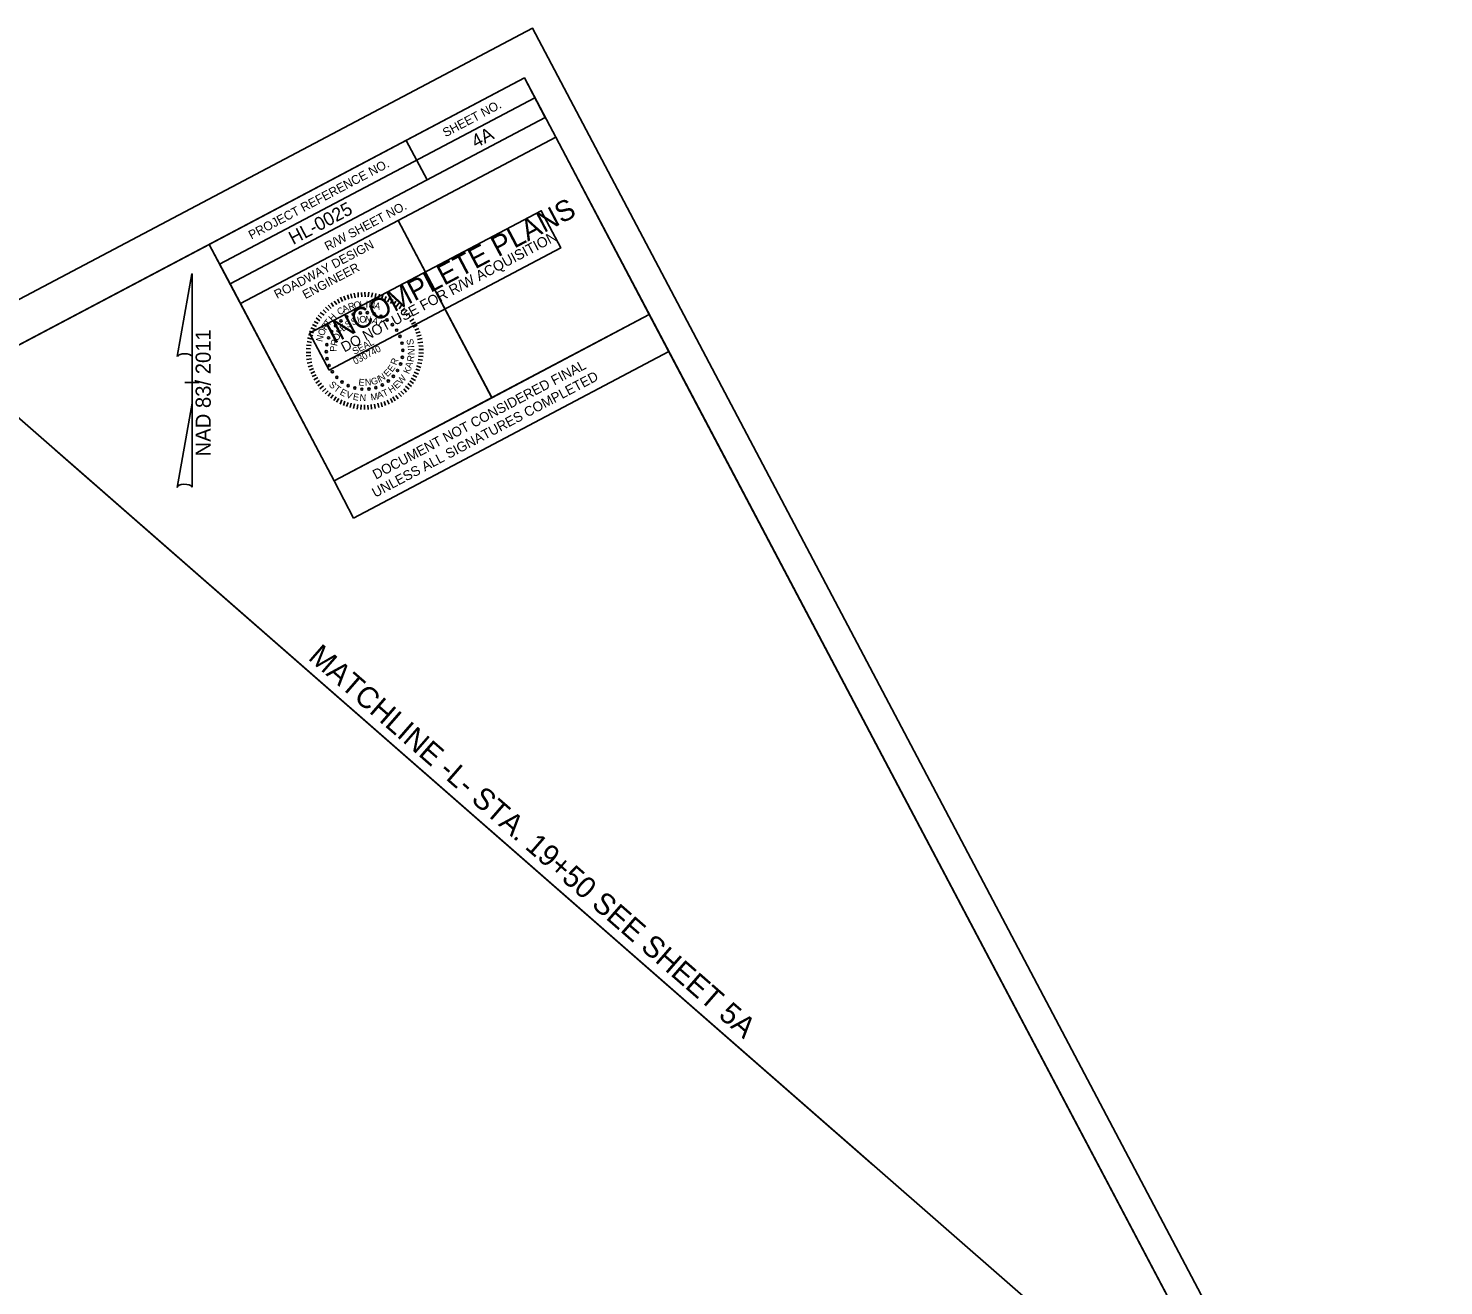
# Model space of a CAD drawing. Extents: x 1486642 to 1489051, y 497560 to 499336.
# Drawn here: x 1488257 to 1489051, y 498631 to 499336 of the extents above; entities that cross this region are included whole.
import ezdxf

# ---------------------------------------------------------------- set-up
doc = ezdxf.new("R2010")
doc.units = 0
for name, color, linetype in [('Matchline', 7, 'Continuous'), ('Matchline Text', 7, 'Continuous'), ('Old_Level_9', 7, 'Continuous'), ('Prop North Arrow NAD83 for Plan Sheets CELL', 7, 'Continuous'), ('Sheet Border Standard 30in CELL', 7, 'Continuous'), ('Sheet Clip Boundary CELL', 7, 'Continuous'), ('Sheet Data Field CELL', 7, 'Continuous'), ('Sheet Plan CELL', 7, 'Continuous'), ('Sheet Plot Border Outside CELL', 7, 'Continuous'), ('Sheet Sticker Exception Certification CELL', 7, 'Continuous'), ('Sheet Sticker Incomplete CELL', 7, 'Continuous')]:
    doc.layers.add(name, color=color, linetype=linetype)

msp = doc.modelspace()

# ---------------------------------------------------------------- linework, layer by layer
at = {"layer": 'Matchline'}
msp.add_line((1488271.73, 499099.83), (1488730.85, 498698.62), dxfattribs=at)
at = {"layer": 'Old_Level_9'}
for p, q in [((1488430.13, 499184.48), (1488431.35, 499182.18)), ((1488431.99, 499185.46), (1488432.94, 499183.02)), ((1488433.81, 499186.08), (1488434.75, 499183.87)), ((1488435.81, 499186.8), (1488436.49, 499184.44)), ((1488437.67, 499187.33), (1488438.18, 499184.88)), ((1488439.63, 499187.69), (1488440.14, 499185.24)), ((1488441.77, 499188.14), (1488441.83, 499185.46)), ((1488443.65, 499188.23), (1488443.93, 499185.77)), ((1488445.61, 499188.36), (1488445.67, 499185.68)), ((1488447.76, 499188.36), (1488447.46, 499185.72)), ((1488449.78, 499187.96), (1488449.39, 499185.49)), ((1488451.76, 499187.65), (1488451.28, 499185.13)), ((1488453.78, 499187.24), (1488453.21, 499184.9)), ((1488455.62, 499186.75), (1488454.92, 499184.23)), ((1488457.61, 499185.99), (1488456.68, 499183.68)), ((1488459.51, 499185.18), (1488458.3, 499182.96)), ((1488420.55, 499176.93), (1488422.73, 499175.37)), ((1488422.13, 499178.44), (1488423.87, 499176.65)), ((1488423.53, 499179.86), (1488425.31, 499177.98)), ((1488425.02, 499181.1), (1488426.58, 499179.21)), ((1488426.74, 499182.35), (1488428.03, 499180.32)), ((1488428.37, 499183.32), (1488429.76, 499181.34)), ((1488461.23, 499184.28), (1488460.02, 499182.06)), ((1488462.99, 499183.29), (1488461.65, 499181.11)), ((1488464.72, 499182.16), (1488463.11, 499180.07)), ((1488466.22, 499181.03), (1488464.83, 499178.94)), ((1488467.91, 499179.55), (1488465.98, 499177.63)), ((1488469.32, 499178.15), (1488467.44, 499176.36)), ((1488470.65, 499176.7), (1488468.68, 499175.09)), ((1488416.18, 499170.22), (1488418.44, 499169.15)), ((1488417.08, 499171.94), (1488419.43, 499170.69)), ((1488418.2, 499173.88), (1488420.38, 499172.32)), ((1488419.42, 499175.43), (1488421.29, 499173.82)), ((1488471.81, 499175.16), (1488469.92, 499173.6)), ((1488472.96, 499173.4), (1488470.8, 499171.92)), ((1488474.03, 499171.59), (1488471.82, 499170.42)), ((1488474.92, 499169.91), (1488472.71, 499168.74)), ((1488413.17, 499160.71), (1488415.6, 499160.18)), ((1488413.4, 499162.64), (1488415.87, 499162.02)), ((1488413.98, 499164.53), (1488416.36, 499163.87)), ((1488414.52, 499166.51), (1488416.82, 499165.58)), ((1488415.32, 499168.41), (1488417.72, 499167.3)), ((1488475.81, 499168), (1488473.6, 499167.06)), ((1488476.62, 499166.05), (1488474.26, 499165.38)), ((1488477.24, 499164.23), (1488474.7, 499163.69)), ((1488477.68, 499162.32), (1488475.14, 499161.77)), ((1488412.59, 499156.67), (1488415.14, 499156.55)), ((1488412.59, 499154.52), (1488415.27, 499154.58)), ((1488412.72, 499152.56), (1488415.31, 499152.8)), ((1488412.81, 499158.6), (1488415.37, 499158.48)), ((1488478.09, 499160.27), (1488475.37, 499159.85)), ((1488478.4, 499154.11), (1488475.8, 499154.32)), ((1488478.31, 499158.13), (1488475.81, 499158.16)), ((1488478.4, 499156.25), (1488475.94, 499156.2)), ((1488412.9, 499150.51), (1488415.58, 499151.01)), ((1488413.26, 499148.55), (1488415.8, 499149.09)), ((1488413.8, 499146.45), (1488416.24, 499147.18)), ((1488414.42, 499144.63), (1488416.77, 499145.54)), ((1488476.43, 499144.35), (1488474.17, 499145.2)), ((1488477.06, 499146.16), (1488474.58, 499147)), ((1488477.55, 499148.23), (1488475.12, 499148.75)), ((1488477.95, 499150.25), (1488475.44, 499150.51)), ((1488478.35, 499152.27), (1488475.67, 499152.43)), ((1488415.22, 499142.68), (1488417.57, 499143.81)), ((1488416.02, 499140.96), (1488418.33, 499141.95)), ((1488417, 499139.1), (1488419.12, 499140.44)), ((1488418.03, 499137.38), (1488420.18, 499138.86)), ((1488419.14, 499135.7), (1488421.16, 499137.22)), ((1488471.75, 499135.44), (1488469.65, 499137.05)), ((1488472.83, 499137.03), (1488470.78, 499138.55)), ((1488473.96, 499138.75), (1488471.6, 499140)), ((1488474.76, 499140.65), (1488472.5, 499141.72)), ((1488475.75, 499142.42), (1488473.27, 499143.48)), ((1488420.34, 499134.07), (1488422.27, 499135.77)), ((1488421.75, 499132.67), (1488423.6, 499134.33)), ((1488423.26, 499131.32), (1488425.06, 499133.06)), ((1488424.9, 499129.93), (1488426.38, 499131.84)), ((1488426.4, 499128.8), (1488427.83, 499130.8)), ((1488428.09, 499127.54), (1488429.56, 499129.67)), ((1488429.72, 499126.59), (1488431.05, 499128.77)), ((1488462.67, 499127.36), (1488461.28, 499129.57)), ((1488464.34, 499128.47), (1488462.96, 499130.46)), ((1488466.06, 499129.72), (1488464.45, 499131.7)), ((1488467.51, 499131.05), (1488465.85, 499132.89)), ((1488469, 499132.29), (1488467.35, 499134.13)), ((1488470.44, 499133.84), (1488468.39, 499135.59)), ((1488431.71, 499125.6), (1488432.73, 499127.95)), ((1488433.51, 499124.75), (1488434.35, 499127.23)), ((1488435.32, 499124.12), (1488436.2, 499126.51)), ((1488437.39, 499123.63), (1488437.91, 499126.05)), ((1488439.23, 499123.13), (1488439.67, 499125.74)), ((1488441.25, 499122.73), (1488441.6, 499125.29)), ((1488443.36, 499122.6), (1488443.48, 499125.15)), ((1488445.33, 499122.51), (1488445.32, 499125.1)), ((1488447.34, 499122.55), (1488447.29, 499125.01)), ((1488449.39, 499122.73), (1488449.16, 499125.32)), ((1488451.4, 499123), (1488450.99, 499125.49)), ((1488453.45, 499123.63), (1488452.77, 499125.98)), ((1488455.36, 499124.07), (1488454.63, 499126.52)), ((1488457.18, 499124.69), (1488456.32, 499126.96)), ((1488459.13, 499125.5), (1488458, 499127.84)), ((1488461.03, 499126.39), (1488459.87, 499128.6))]:
    msp.add_line(p, q, dxfattribs=at)
for centre in [(1488439.13, 499175.89), (1488443.01, 499176.7), (1488446.97, 499176.78), (1488450.89, 499176.13), (1488429.25, 499169.5), (1488432.13, 499172.23), (1488435.46, 499174.39), (1488454.61, 499174.77), (1488458.02, 499172.75), (1488461.01, 499170.14), (1488425.23, 499162.71), (1488426.93, 499166.29), (1488463.46, 499167.02), (1488465.3, 499163.51), (1488423.93, 499154.92), (1488424.22, 499158.87), (1488466.46, 499159.72), (1488466.9, 499155.77), (1488424.38, 499150.98), (1488425.54, 499147.19), (1488463.91, 499144.4), (1488465.61, 499147.98), (1488466.61, 499151.82), (1488427.38, 499143.67), (1488429.83, 499140.56), (1488432.81, 499137.94), (1488455.38, 499136.31), (1488458.71, 499138.46), (1488461.58, 499141.19), (1488436.22, 499135.92), (1488439.95, 499134.57), (1488443.86, 499133.92), (1488447.83, 499133.99), (1488451.71, 499134.8)]:
    msp.add_circle(centre, 0.63, dxfattribs=at)
at = {"layer": 'Prop North Arrow NAD83 for Plan Sheets CELL'}
for p, q in [((1488340.33, 499152.33), (1488348.53, 499198.68)), ((1488348.58, 499198.68), (1488348.53, 499198.68)), ((1488348.58, 499198.68), (1488348.53, 499198.68)), ((1488348.58, 499198.68), (1488348.58, 499150.88)), ((1488348.58, 499126.08), (1488348.58, 499152.28)), ((1488348.58, 499150.88), (1488348.58, 499152.23)), ((1488344.58, 499137.68), (1488344.53, 499137.68)), ((1488348.13, 499137.68), (1488344.58, 499137.68)), ((1488344.63, 499137.68), (1488352.63, 499137.68)), ((1488348.58, 499126.08), (1488340.23, 499078.83)), ((1488348.63, 499079.03), (1488348.58, 499126.08))]:
    msp.add_line(p, q, dxfattribs=at)
for centre, start_param, end_param in [((1488344.46, 499151.83), 0.216388, 2.908219), ((1488344.46, 499078.66), 0.201328, 3.141593)]:
    msp.add_ellipse(centre, major_axis=(4.23, -0.03), ratio=0.461098, start_param=start_param, end_param=end_param, dxfattribs=at)
at = {"layer": 'Sheet Border Standard 30in CELL'}
msp.add_line((1488369.9, 499192.95), (1488375.74, 499181.9), dxfattribs=at)
at = {"layer": 'Sheet Clip Boundary CELL'}
msp.add_lwpolyline([(1487208.67, 498608.12), (1488222.07, 499143.22), (1488965.38, 498493.67), (1489025.4, 498380.01), (1487698.94, 497679.61)], close=True, dxfattribs=at)
at = {"layer": 'Sheet Plan CELL'}
for p, q in [((1488364.06, 499204.02), (1488540.97, 499297.41)), ((1488369.93, 499192.94), (1488546.81, 499286.36)), ((1488468.8, 499273.43), (1488480.51, 499251.34)), ((1488464.23, 499228.61), (1488516.75, 499129.17)), ((1488369.93, 499192.94), (1488375.76, 499181.89))]:
    msp.add_line(p, q, dxfattribs=at)
for points in [[(1488535.14, 499308.53), (1487208.67, 498608.12), (1487698.94, 497679.61), (1489025.4, 498380.01)], [(1488358.21, 499215.12), (1488535.14, 499308.53), (1488546.81, 499286.36), (1488369.93, 499192.94)], [(1488464.23, 499228.61), (1488552.64, 499275.31), (1488605.19, 499175.82), (1488516.77, 499129.11)], [(1488375.76, 499181.89), (1488464.23, 499228.61), (1488516.77, 499129.11), (1488428.29, 499082.43)], [(1487698.94, 497679.61), (1487208.66, 498608.09), (1488358.21, 499215.12), (1488428.29, 499082.43), (1488605.19, 499175.82), (1489025.4, 498380.01)]]:
    msp.add_lwpolyline(points, close=True, dxfattribs=at)
at = {"layer": 'Sheet Plot Border Outside CELL'}
msp.add_lwpolyline([(1487562.23, 497581.96), (1489050.94, 498368.04), (1488539.66, 499336.34), (1487050.94, 498550.27)], close=True, dxfattribs=at)
at = {"layer": 'Sheet Sticker Exception Certification CELL'}
for p, q in [((1488428.29, 499082.43), (1488605.18, 499175.83)), ((1488605.19, 499175.82), (1488616.16, 499155.04)), ((1488616.16, 499155.05), (1488439.27, 499061.65)), ((1488439.27, 499061.65), (1488428.29, 499082.43))]:
    msp.add_line(p, q, dxfattribs=at)
at = {"layer": 'Sheet Sticker Incomplete CELL'}
msp.add_lwpolyline([(1488425.5, 499144.55), (1488414.53, 499165.33), (1488544.52, 499233.97), (1488555.49, 499213.19)], close=True, dxfattribs=at)

# ---------------------------------------------------------------- texts
at = {"layer": 'Matchline Text'}
msp.add_text('MATCHLINE -L- STA. 19+50 SEE SHEET 5A', height=12, rotation=318.92761, dxfattribs=at).set_placement((1488413.21, 498982.68))
at = {"layer": 'Old_Level_9'}
for s, height, rotation, p in [('H', 3.78, 45.57844, (1488427.42, 499171.63)), ('C', 3.78, 32.77501, (1488431.41, 499175.21)), ('A', 3.78, 25.80995, (1488433.88, 499176.74)), ('R', 3.78, 17.85665, (1488436.89, 499178.1)), ('O', 3.78, 10.92189, (1488439.69, 499179.01)), ('L', 3.78, 3.581, (1488442.77, 499179.62)), ('I', 3.78, 358.64105, (1488445.98, 499179.73)), ('N', 3.78, 352.73893, (1488447.46, 499179.72)), ('A', 3.78, 344.84016, (1488450.56, 499179.21)), ('R', 3.78, 60.01054, (1488423.86, 499166.58)), ('T', 3.78, 53.27087, (1488425.33, 499168.94)), ('F', 3.76, 54.23505, (1488432.15, 499163.95)), ('E', 3.76, 44.42402, (1488433.59, 499165.95)), ('S', 3.76, 32.30312, (1488435.86, 499168.06)), ('S', 3.76, 20.87655, (1488438.65, 499169.64)), ('I', 3.76, 13.31716, (1488441.66, 499170.78)), ('O', 3.76, 5.70998, (1488442.64, 499171.07)), ('N', 3.76, 355.22811, (1488445.54, 499171.36)), ('A', 3.76, 341.77886, (1488449.18, 499170.9)), ('L', 3.76, 329.3674, (1488452.56, 499169.64)), ('N', 3.78, 75.90175, (1488421.68, 499160.23)), ('O', 3.78, 67.77931, (1488422.46, 499163.47)), ('R', 3.76, 77.58289, (1488429.92, 499157.91)), ('O', 3.76, 66.08691, (1488430.57, 499160.74)), ('SEAL', 3.759, 27.83509, (1488439.72, 499153.17)), ('S', 3.78, 100.09298, (1488473.17, 499159.04)), ('P', 3.76, 87.95873, (1488429.72, 499154.86)), ('030740', 3.759, 27.83509, (1488440.19, 499147.58)), ('R', 3.78, 78.98541, (1488472.75, 499148.95)), ('I', 3.78, 93.88149, (1488473.34, 499157.22)), ('N', 3.78, 87.20766, (1488473.41, 499152.96)), ('E', 3.76, 43.64078, (1488458.22, 499140.51)), ('E', 3.76, 54.9919, (1488460.97, 499143.21)), ('R', 3.76, 68.18435, (1488463.21, 499147.1)), ('K', 3.78, 63.9761, (1488470.29, 499142.06)), ('A', 3.78, 71.35678, (1488471.55, 499145.3)), ('S', 3.78, 316.0471, (1488425.11, 499136.06)), ('E', 3.76, 352.70428, (1488441.76, 499136.12)), ('N', 3.76, 3.89345, (1488445.7, 499135.93)), ('G', 3.76, 15.31634, (1488449.54, 499136.15)), ('I', 3.76, 23.45968, (1488453.41, 499137.4)), ('N', 3.76, 30.96288, (1488454.47, 499137.96)), ('E', 3.78, 41.99985, (1488463.45, 499133.79)), ('W', 3.78, 49.84085, (1488466.06, 499136.26)), ('T', 3.78, 323.45948, (1488427.81, 499133.5)), ('E', 3.78, 331.65758, (1488431.18, 499131.12)), ('V', 3.78, 339.76489, (1488434.67, 499129.36)), ('E', 3.78, 348.06633, (1488438.61, 499128.08)), ('N', 3.78, 356.16408, (1488442.51, 499127.4)), ('M', 3.78, 10.17213, (1488449.14, 499127.5)), ('A', 3.78, 18.01726, (1488453.06, 499128.41)), ('T', 3.78, 25.22168, (1488456.33, 499129.51)), ('H', 3.78, 33.84631, (1488460.23, 499131.44))]:
    msp.add_text(s, height=height, rotation=rotation, dxfattribs=at).set_placement(p)
at = {"layer": 'Prop North Arrow NAD83 for Plan Sheets CELL'}
msp.add_text('NAD 83/ 2011', height=8.5, rotation=90, dxfattribs=at).set_placement((1488359.1, 499096.16))
at = {"layer": 'Sheet Data Field CELL'}
for s, p in [('4A', (1488507.86, 499268.96)), ('HL-0025', (1488405.34, 499214.76))]:
    msp.add_text(s, height=7.5, rotation=27.8351, dxfattribs=at).set_placement(p)
at = {"layer": 'Sheet Plan CELL'}
for s, height, p in [('SHEET NO.', 5, (1488490.88, 499275.18)), ('PROJECT REFERENCE NO.', 5.0001, (1488381.92, 499217.77)), ('R/W SHEET NO.', 5.0001, (1488424.62, 499211.43)), ('ROADWAY DESIGN', 5.0001, (1488396.3, 499184.48)), ('ENGINEER', 5, (1488412.19, 499184.35))]:
    msp.add_text(s, height=height, rotation=27.8351, dxfattribs=at).set_placement(p)
at = {"layer": 'Sheet Sticker Exception Certification CELL'}
for s, p in [('DOCUMENT NOT CONSIDERED FINAL', (1488451.76, 499083.12)), ('UNLESS ALL SIGNATURES COMPLETED', (1488451.38, 499072.97))]:
    msp.add_text(s, height=5.5, rotation=27.83509, dxfattribs=at).set_placement(p)
at = {"layer": 'Sheet Sticker Incomplete CELL'}
for s, height, p in [('INCOMPLETE PLANS', 11.52, (1488427.95, 499159.07)), ('DO NOT USE FOR R/W ACQUISITION', 5.76, (1488434.07, 499154.45))]:
    msp.add_text(s, height=height, rotation=27.83509, dxfattribs=at).set_placement(p)

doc.saveas('drawing.dxf')
